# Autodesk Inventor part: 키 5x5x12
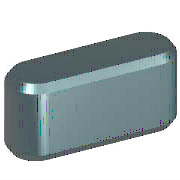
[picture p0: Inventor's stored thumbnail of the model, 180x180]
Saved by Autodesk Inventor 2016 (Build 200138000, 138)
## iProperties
IsCustomPart: 1
Created: 2012-02
Part Number: 키 5x5x12
Material: 강철, 연강
Description: 키 및 해당 키홈
Document SubType Name: Modeling
Standard: KS B 1311
Designer: mduedu
Standards Organization: KS
Language: ko-KR
Size Designation: 5 x 5 x 12
Categories: <MemberInstance><Categories><Category DisplayName="샤프트 부품" InternalName="7f7aeb1f-a693-4053-b835-cee3144e0d98" Mnemonic="SHFT"><Category DisplayName="키" Interna
Density: 1 g/cm^3
Appearance: 노란색
Author: mduedu
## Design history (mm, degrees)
workplane "Work Plane1"
workplane "Work Plane2"
sketch "스케치1"
  geometry: L1 (2.5, 2.5)-(9.5, 2.5); L2 (9.5, -2.5)-(2.5, -2.5); L3 (0, 9.4)-(0, -7.4) reference; L4 (-5, 0)-(30, 0) reference; L5 (12, 0)-(12, 7); A1 r 2.5 centre (2.5, 0) between (2.5, 2.5) and (2.5, -2.5); A2 r 2.5 centre (9.5, 0) between (9.5, -2.5) and (9.5, 2.5)
  constraints: 6 end point, 5 point on circle, 4 tangent, 3 point on line, 2 centre point, 1 horizontal, 1 parallel, 1 perpendicular
  dimensions: "d0" = 2.5 radius of A1 (= 0.5 x PB); "d13" = 2.5 radius of A2 (= 0.5 x PB); "d14" = 12 distance between parallel lines of L5 L3 (= NLG)
extrude "본체1" new body sketch "스케치1" taper "d3" = 0 deg; stored distance "d4" = 10
workplane "Work Plane3"
body "Solid1"
chamfer "모따기1" distance "d8" = 0.4 (= PHH); stored, may be unused: second distance "d9" = 0.4 (= PHH), angle "d15" = 45 deg
other parameters: "d1" = -3 (= -PNT), "d2" = 2 (= PH - PNT), "NLG" = 12 [user parameter; used in 3 equation terms], "PB" = 5 [user parameter; used in 2 equation terms], "PNT" = 3 [user parameter; used in 2 equation terms], "PH" = 5 [user parameter; used in 1 equation term], "PHH" = 0.4 [user parameter; used in 2 equation terms], "d10" = 0, "d16" = 0, "d17" = 0, "d18" = 0, "WDMIN" = 12 [user parameter], "PLB2" = 12 (= NLG) [user parameter], "WDMAX" = 17 [user parameter], "PLB1" = 12 (= NLG) [user parameter], "RR" = 0.16 [user parameter], "PUEB" = 2.3 [user parameter]
